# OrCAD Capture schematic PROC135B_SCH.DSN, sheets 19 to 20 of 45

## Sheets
19 19. eMMC FLASH: size C; title: SOC MMC0..2 INTERFACE, eMMC FLASH AND eMMC FLASH RESET
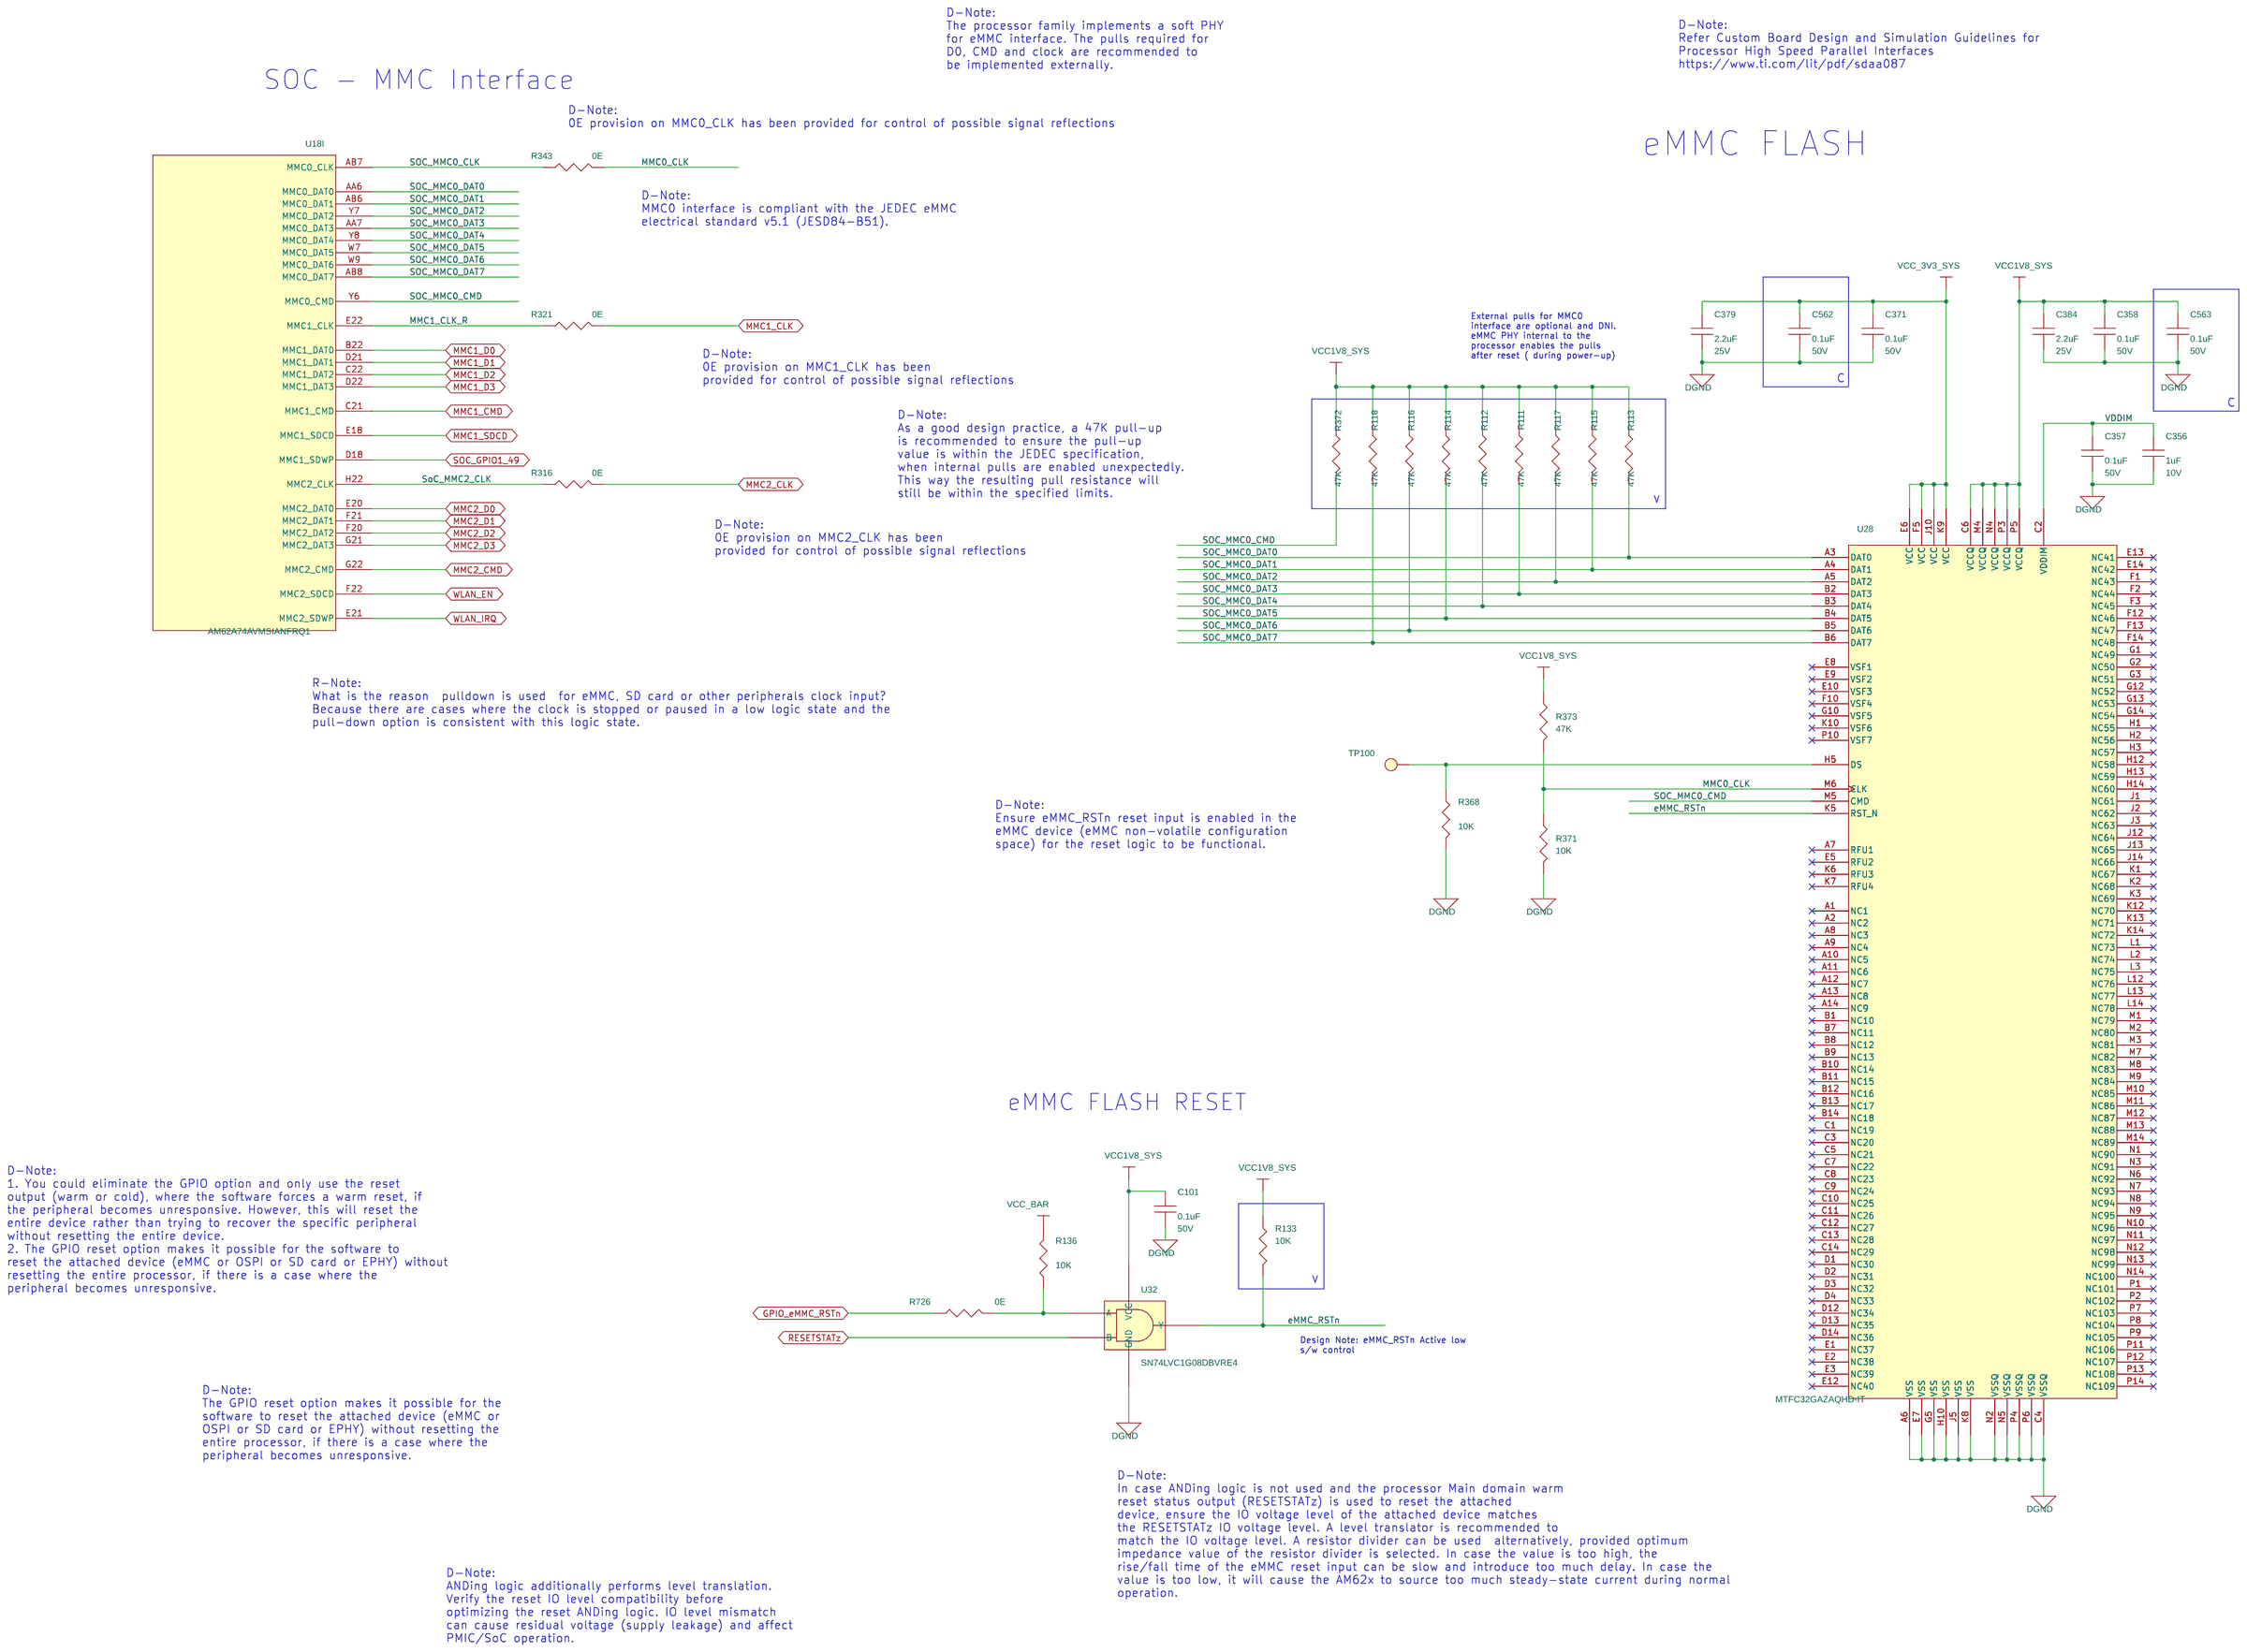
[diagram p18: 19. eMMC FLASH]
20 20. SD CARD INTERFACE: size C; title: SD CARD - LOAD SWITCH, LOAD SWITCH RESET LOGIC AND DATA INTERFACE
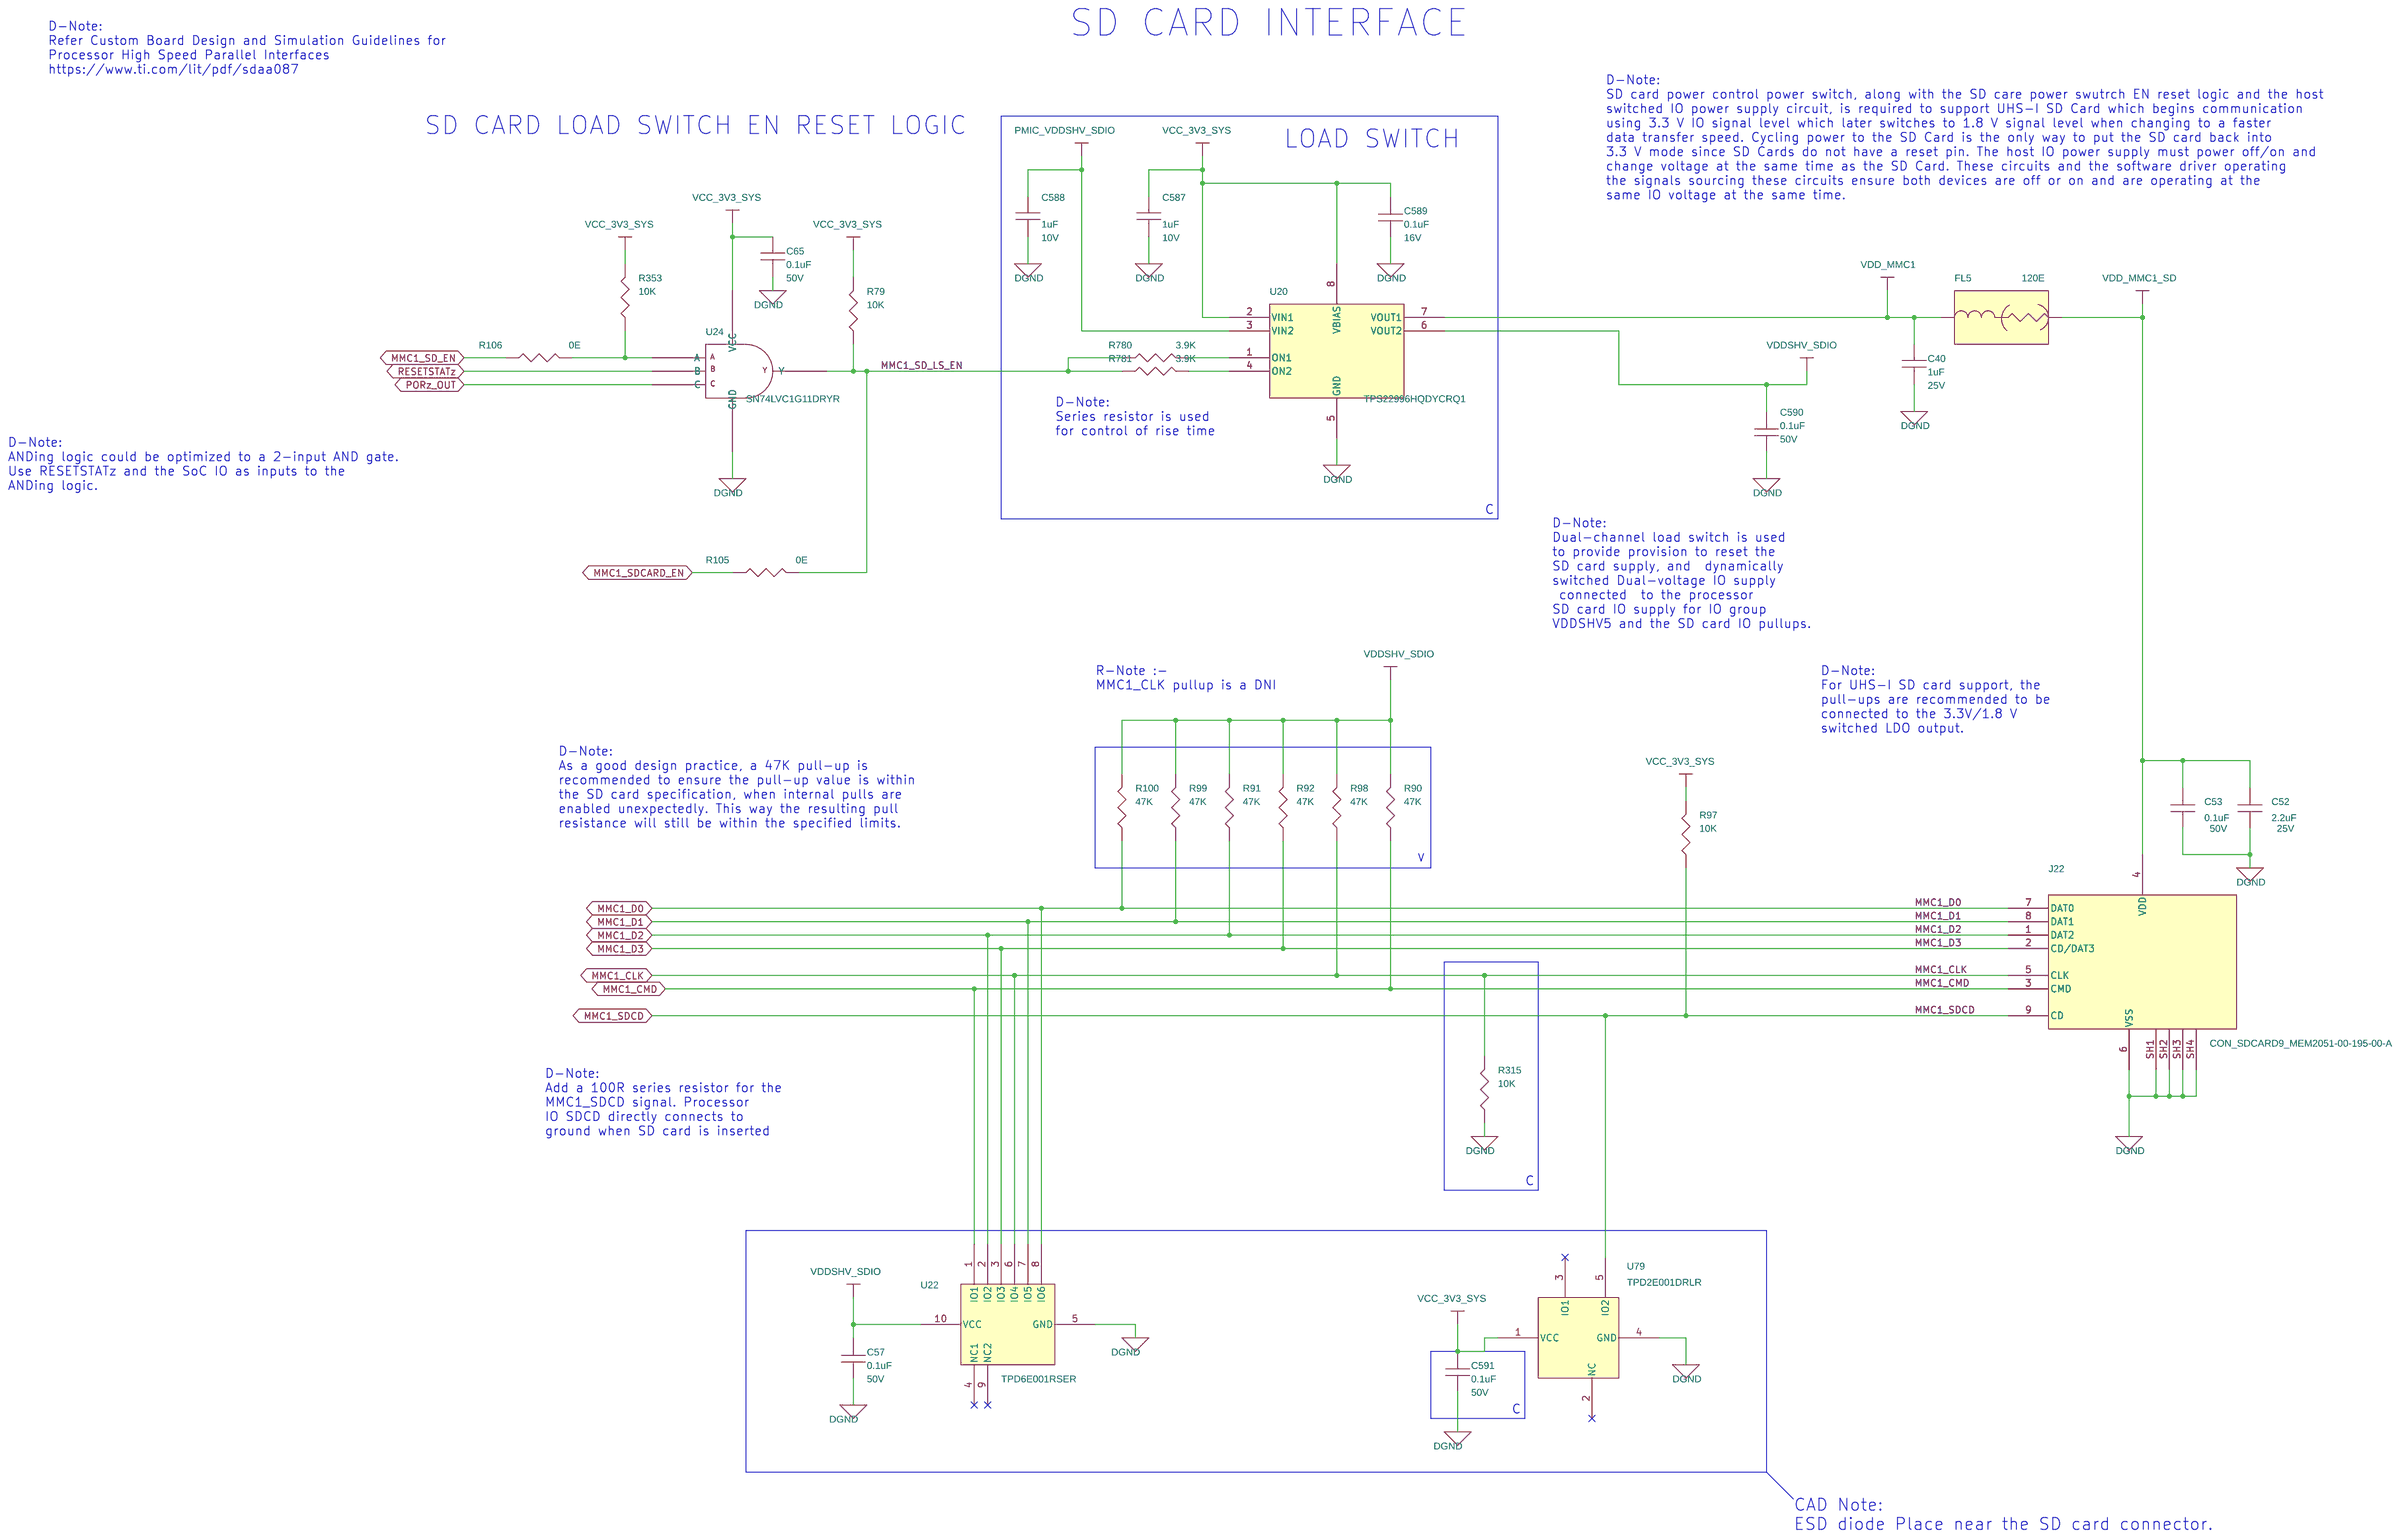
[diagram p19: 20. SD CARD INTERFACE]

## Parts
sheet 19. eMMC FLASH
C101  0.1uF  [CAP0402_0-75]
C356  1uF  [CAP0201_0-5]
C357  0.1uF  [CAP0402_0-75]
C358  0.1uF  [CAP0402_0-75]
C371  0.1uF  [CAP0402_0-75]
C379  2.2uF  [CAP0402_0-75]
C384  2.2uF  [CAP0402_0-75]
C562  0.1uF  [CAP0402_0-75]
C563  0.1uF  [CAP0402_0-75]
R111  47K  [RES0201_0-5]
R112  47K  [RES0201_0-5]
R113  47K  [RES0201_0-5]
R114  47K  [RES0201_0-5]
R115  47K  [RES0201_0-5]
R116  47K  [RES0201_0-5]
R117  47K  [RES0201_0-5]
R118  47K  [RES0201_0-5]
R133  10K  [RES0402_0-5]
R136  10K  [RES0201_0-5]
R316  0E  [RES0201_0-5]
R321  0E  [RES0201_0-5]
R343  0E  [RES0201_0-5]
R368  10K  [RES0201_0-5]
R371  10K  [RES0201_0-5]
R372  47K  [RES0201_0-5]
R373  47K  [RES0201_0-5]
R726  0E  [RES0402_0-5]
TP100  TP20_SMD  [TP20_SMD]
U28  MTFC32GAZAQHD-IT  [VFBGA153_19-68_460X520_0-9_CUSTOM]
U32  SN74LVC1G08DBVRE4  [SOT23-5]
sheet 20. SD CARD INTERFACE
C40  1uF  [CAP0402_0-75]
C52  2.2uF  [CAP0402_0-75]
C53  0.1uF  [CAP0402_0-75]
C57  0.1uF  [CAP0402_0-75]
C65  0.1uF  [CAP0402_0-75]
C587  1uF  [CAP0201_0-5]
C588  1uF  [CAP0201_0-5]
C589  0.1uF  [CAP0201_0-5]
C590  0.1uF  [CAP0402_0-75]
C591  0.1uF  [CAP0402_0-75]
FL5  120E  [EMIFIL_BLM15A_0402_0-6]
J22  CON_SDCARD9_MEM2051-00-195-00-A  [CON_SD9_MEM2051-00-195-00_S_R_S_2-1]
R79  10K  [RES0201_0-5]
R90  47K  [RES0201_0-5]
R91  47K  [RES0201_0-5]
R92  47K  [RES0201_0-5]
R97  10K  [RES0201_0-5]
R98  47K  [RES0201_0-5]
R99  47K  [RES0201_0-5]
R100  47K  [RES0201_0-5]
R105  0E  [RES0201_0-5]
R106  0E  [RES0201_0-5]
R315  10K  [RES0201_0-5]
R353  10K  [RES0201_0-5]
R780  3.9K  [RES0402_0-5]
R781  3.9K  [RES0402_0-5]
U20  TPS22996HQDYCRQ1  [SOT5X3-8_0-6]
U22  TPD6E001RSER  [UQFN10_19-68_80X60_0-6]
U24  SN74LVC1G11DRYR  [SON6_SN74LVC2G17_40X60_0-6]
U79  TPD2E001DRLR  [SOT553-5_0-6]
sheet 34. MCU HEADER
U18  AM62A74AVMSIANFRQ1  [FBGA484_31-49_710X710_2-7]  (sections A,B,C,D,E,F,G,H,I,J,K,L,M,N,O,P,Q)

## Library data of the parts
C53 C57 C65 C101 C357 C358 C371 C562 C563 C590 C591 = CAP: CAP CERAMIC 0.1uF 50V 10% X7R AUTO 0402; Alt_Mfr_name: YAGEO AMERICA; Alt_Mfr_part_number: CC0402KRX5R8BB104; Chkd/date: MANIRAJA/250221; Crtd /date: ALVY/240221; Custom_Duty: 15%; Customs_HS_Code: 85322990; Distributor_name: MOUSER; Distributor_part_number: 81-GRT155R71H104KE1D; Footprint Path: Y:\MIS_DATABASE\Library\ALTIUM_TOOL\PCB_FOOTPRINTS\Altium_Footprint_Lib.PcbLib; Height: 0.55MM; Library Path: Y:\MIS_DATABASE\Library\ALTIUM_TOOL\SCHEMATICS_PARTS\MS_DISCRETE_Library.schlib; Mfr_name: MURATA; Mfr_part_number: GRT155R71H104KE01D; Mistral Part No: 120019030005-R; Package: 0402; Part_type: CAPACITORS\CERAMIC; Project: TI_DRA821 SK EVM BRD; RoHS: RoHS; Temperature: -55°C+125°C; Tolerance: 10%; Voltage: 50V; Wattage: NA; Weight: NA; Datasheet: Y:\MIS_DATABASE\DATASHEETS\CAPACITORS\GRT155R71H104KE01.PDF
C356 C587 C588 = CAP: CAP CERAMIC 1uF 10V 20% X6S 0201; Chkd/date: PRADEEP/130623; Crtd /date: PRADEEP/130623; Custom_Duty: 15%; Customs_HS_Code: 85322990; Distributor_name: DIGIKEY; Distributor_part_number: 490-GRT033C81A105ME13DTR-ND; Footprint Path: Y:\MIS_DATABASE\Library\ALTIUM_TOOL\PCB_FOOTPRINTS\Altium_Footprint_Lib.PcbLib; Height: 0.39MM; Library Path: Y:\MIS_DATABASE\Library\ALTIUM_TOOL\SCHEMATICS_PARTS\MS_DISCRETE_Library.schlib; Mfr_name: MURATA; Mfr_part_number: GRT033C81A105ME13D; Mistral Part No: 120022060020-R; Package: 0201; Part_type: CAPACITORS\CERAMIC; Project: AM62P_SK; RoHS: RoHS; Temperature: -55°C+105°C; Tolerance: 20%; Voltage: 10V; Wattage: NA; Weight: NA; Datasheet: Y:\MIS_DATABASE\DATASHEETS\CAPACITORS\GRT033C81A105ME13D.PDF
C52 C379 C384 = CAP: CAP CERAMIC 2.2uF 25V 10% X5R AUTO 0402; Chkd/date: MANIRAJA/240920; Crtd /date: ALVY/240920; Custom_Duty: 15%; Customs_HS_Code: 85322990; Distributor_name: DIGIKEY; Distributor_part_number: 490-12267-1-ND; Footprint Path: Y:\MIS_DATABASE\Library\ALTIUM_TOOL\PCB_FOOTPRINTS\Altium_Footprint_Lib.PcbLib; Height: 0.70MM; Library Path: Y:\MIS_DATABASE\Library\ALTIUM_TOOL\SCHEMATICS_PARTS\MS_DISCRETE_Library.schlib; Mfr_name: MURATA; Mfr_part_number: GRT155R61E225KE13D; Mistral Part No: 120020090019-R; Package: 0402; Part_type: CAPACITORS\CERAMIC; Project: ECU_RO; RoHS: RoHS; Temperature: -55°C+85°C; Tolerance: 10%; Voltage: 25V; Wattage: NA; Weight: 0.65mg; Datasheet: Y:\MIS_DATABASE\DATASHEETS\CAPACITORS\GRT155R61E225KE13.PDF
R90-R92 R98-R100 R111-R118 R372 R373 = RESISTOR: RES 47K 1/20W 5% 0201; Chkd/date: MAZHAR/121207; Crtd /date: USMAN/121207; Custom_Duty: 15%; Customs_HS_Code: 85332119; Distributor_name: DIGIKEY; Distributor_part_number: P47KAGCT-ND; Footprint Path: Y:\MIS_DATABASE\Library\ALTIUM_TOOL\PCB_FOOTPRINTS\Altium_Footprint_Lib.PcbLib; Height: 0.26MM; Library Path: Y:\MIS_DATABASE\Library\ALTIUM_TOOL\SCHEMATICS_PARTS\MS_DISCRETE_Library.schlib; Mfr_name: PANASONIC-ECG; Mfr_part_number: ERJ-1GEJ473C; Mistral Part No: 110009030881-R; Package: 0201; Part_type: RESISTORS\FIXED; Project: SD_WATERLOO; RoHS: RoHS; Temperature: -55°C+125°C; Tolerance: 5%; Voltage: NA; Wattage: 1/20W; Weight: 0.15mg; Datasheet: Y:\MIS_DATABASE\DATASHEETS\RESISTORS\PAN-ERJXGE-FEB06.PDF
R133 = RESISTOR: RES 10K 1/16W 5% 0402; Chkd/date: MANIRAJA/120219; Crtd /date: MANIRAJA/120219; Custom_Duty: 15%; Customs_HS_Code: 85332119; Distributor_name: DIGIKEY; Distributor_part_number: 541-10KJCT-ND; Footprint Path: Y:\MIS_DATABASE\Library\ALTIUM_TOOL\PCB_FOOTPRINTS\Altium_Footprint_Lib.PcbLib; Height: 0.40MM; Library Path: Y:\MIS_DATABASE\Library\ALTIUM_TOOL\SCHEMATICS_PARTS\MS_DISCRETE_Library.schlib; Mfr_name: VISHAY; Mfr_part_number: CRCW040210K0JNED; Mistral Part No: 110011060021-R; Package: 0402; Part_type: RESISTORS\FIXED; Project: NEXTNAV_ORBIT_MODULE; RoHS: RoHS; Temperature: -55°C+155°C; Tolerance: 5%; Voltage: NA; Wattage: 1/16W; Weight: 0.65mg; Datasheet: Y:\MIS_DATABASE\DATASHEETS\RESISTORS\CRCW0603.PDF
R79 R97 R136 R315 R353 R368 R371 = RESISTOR: RES 10K 1/20W 5% 0201; Chkd/date: MANIRAJA/050517; Crtd /date: MANIRAJA/050517; Custom_Duty: 15%; Customs_HS_Code: 85332119; Distributor_name: DIGIKEY; Distributor_part_number: 311-10KNCT-ND; Footprint Path: Y:\MIS_DATABASE\Library\ALTIUM_TOOL\PCB_FOOTPRINTS\Altium_Footprint_Lib.PcbLib; Height: 0.26MM; Library Path: Y:\MIS_DATABASE\Library\ALTIUM_TOOL\SCHEMATICS_PARTS\MS_DISCRETE_Library.schlib; Mfr_name: YAGEO AMERICA; Mfr_part_number: RC0201JR-0710KL; Mistral Part No: 110010070051-R; Package: 0201; Part_type: RESISTORS\FIXED; Project: GOLDEN-I LITE; RoHS: RoHS; Temperature: -55°C+125°C; Tolerance: 5%; Voltage: NA; Wattage: 1/20W; Weight: 0.17mg; Datasheet: Y:\MIS_DATABASE\DATASHEETS\RESISTORS\RCXXXXL-SER_MAR18.PDF
R316 R321 = RESISTOR: RES 0E 1/20W 5% 0201; Chkd/date: NAVEED/301214; Crtd /date: MUDDU/120710; Custom_Duty: 15%; Customs_HS_Code: 85332119; Distributor_name: DIGIKEY; Distributor_part_number: 311-0.0NCT-ND; Footprint Path: Y:\MIS_DATABASE\Library\ALTIUM_TOOL\PCB_FOOTPRINTS\Altium_Footprint_Lib.PcbLib; Height: 0.26MM; Library Path: Y:\MIS_DATABASE\Library\ALTIUM_TOOL\SCHEMATICS_PARTS\MS_DISCRETE_Library.schlib; Mfr_name: YAGEO AMERICA; Mfr_part_number: RC0201JR-070RL; Mistral Part No: 110010070067-R; Package: 0201; Part_type: RESISTORS\FIXED; Project: PB_BUGBASE; RoHS: RoHS; SIGNAL_MODEL: RESISTOR_RES0201_0-5_0E_0E; Temperature: -55°C+125°C; Tolerance: 5%; Voltage: NA; Wattage: 1/20W; Weight: 0.17mg; Datasheet: Y:\MIS_DATABASE\DATASHEETS\RESISTORS\RCXXXXL-SER_MAR18.PDF
R343 = RESISTOR: RES 0E 1/20W 5% 0201; Chkd/date: NAVEED/301214; Crtd /date: MUDDU/120710; Custom_Duty: 15%; Customs_HS_Code: 85332119; Distributor_name: DIGIKEY; Distributor_part_number: 311-0.0NCT-ND; Footprint Path: Y:\MIS_DATABASE\Library\ALTIUM_TOOL\PCB_FOOTPRINTS\Altium_Footprint_Lib.PcbLib; Height: 0.26MM; Library Path: Y:\MIS_DATABASE\Library\ALTIUM_TOOL\SCHEMATICS_PARTS\MS_DISCRETE_Library.schlib; Mfr_name: YAGEO AMERICA; Mfr_part_number: RC0201JR-070RL; Mistral Part No: 110010070067-R; Package: 0201; Part_type: RESISTORS\FIXED; Project: PB_BUGBASE; RoHS: RoHS; SIGNAL_MODEL: RESISTOR_RES0201_0-5_22E_1%_22E_1%; Temperature: -55°C+125°C; Tolerance: 5%; Voltage: NA; Wattage: 1/20W; Weight: 0.17mg; Datasheet: Y:\MIS_DATABASE\DATASHEETS\RESISTORS\RCXXXXL-SER_MAR18.PDF
R726 = RESISTOR: RES 0E 1/16W JUMPER 0402; Chkd/date: VASANTHA/201216; Crtd /date: MUDDU/190810; Custom_Duty: 15%; Customs_HS_Code: 85332119; Distributor_name: DIGIKEY; Distributor_part_number: 541-0.0JCT-ND; Footprint Path: Y:\MIS_DATABASE\Library\ALTIUM_TOOL\PCB_FOOTPRINTS\Altium_Footprint_Lib.PcbLib; Height: 0.40MM; Library Path: Y:\MIS_DATABASE\Library\ALTIUM_TOOL\SCHEMATICS_PARTS\MS_DISCRETE_Library.schlib; Mfr_name: VISHAY; Mfr_part_number: CRCW04020000Z0ED; Mistral Part No: 110010080019-R; Package: 0402; Part_type: RESISTORS\FIXED; Project: PB_BUGBASE; RoHS: RoHS; Temperature: -55°C+155°C; Tolerance: NA; Voltage: NA; Wattage: 1/16W; Weight: 0.65mg; Datasheet: Y:\MIS_DATABASE\DATASHEETS\RESISTORS\CRCW0603.PDF
TP100 = TESTPOINT: TESTPOINT CIR 20 SMD; Chkd/date: SHREESHAIL/171006; Crtd /date: MAZHAR/171006; Custom_Duty: NA; Customs_HS_Code: NA; Distributor_name: NA; Distributor_part_number: NA; Footprint Path: Y:\MIS_DATABASE\Library\ALTIUM_TOOL\PCB_FOOTPRINTS\Altium_Footprint_Lib.PcbLib; Height: NA; Library Path: Y:\MIS_DATABASE\Library\ALTIUM_TOOL\SCHEMATICS_PARTS\MS_DISCRETE_Library.schlib; MECHANICAL 3D STEP FILE: NA; Mfr_name: LOCAL; Mistral Part No: NA; Package: SMD; Project: BT MODULE_CSRBC04; RoHS: NA; Temperature: NA; Tolerance: NA; Voltage: NA; Wattage: NA; Weight: NA; Datasheet: NA
U28 = MTFC16GAPALBH_TFBGA153: IC 32GB e-MMC MEMORY VFBGA153; Chkd/date: PRAVEEN/010922; Crtd /date: PRAVEEN/010922; Custom_Duty: 15%; Customs_HS_Code: 85423100; Distributor_name: DIGIKEY; Distributor_part_number: 557-MTFC32GAZAQHD-IT-ND; Footprint Path: Y:\MIS_DATABASE\Library\ALTIUM_TOOL\PCB_FOOTPRINTS\Altium_Footprint_Lib.PcbLib; Height: 0.90MM; Library Path: Y:\MIS_DATABASE\Library\ALTIUM_TOOL\SCHEMATICS_PARTS\MS_MISCMEMORY_Library.schlib; MECHANICAL 3D STEP FILE: VFBGA153_19-68_460X520_0-9; Mfr_name: MICRON; Mfr_part_number: MTFC32GAZAQHD-IT_CUSTOM; Mistral Part No: NA; Package: VFBGA153; Part_type: ICS\DIGITAL\MEMORY; Project: J7AEN_SK_EVM; RoHS: RoHS; Temperature: -40°C+95°C; Tolerance: NA; Voltage: NA; Wattage: NA; Weight: NA; Datasheet: Y:\MIS_DATABASE\DATASHEETS\ICS\MEMORY\MTFC64GAZAQHD-IT.PDF
U32 = SN74LVC1G08DBVRE4_SOT23-5: IC SINGLE 2-INPUT POSITIVE AND GATE SOT23-5; Chkd/date: SUHAS/221010; Crtd /date: USMAN/151008; Custom_Duty: 15%; Customs_HS_Code: 85423100; Distributor_name: DIGIKEY; Distributor_part_number: SN74LVC1G08DBVRE4-ND; Height: 1.45MM; Mfr_name: TEXAS INSTRUMENTS; Mistral Part No: 141009060026-R; Part_type: ICS\DIGITAL\GATES; Project: KHAN_MAIN; RoHS: Sb/ Br FREE; Temperature: -40°C+85°C; Datasheet: Y:\MIS_DATABASE\DATASHEETS\ICS\DIGITAL\GATES\SN74LVC1G08.PDF
C40 = CAP: CAP CERAMIC 1uF 25V 10% X5R AUTO 0402; Chkd/date: MANIRAJA/290318; Crtd /date: ALVY/280318; Custom_Duty: 15%; Customs_HS_Code: 85322990; Distributor_name: DIGIKEY; Distributor_part_number: 490-12263-1-ND; Footprint Path: Y:\MIS_DATABASE\Library\ALTIUM_TOOL\PCB_FOOTPRINTS\Altium_Footprint_Lib.PcbLib; Height: 0.55MM; Library Path: Y:\MIS_DATABASE\Library\ALTIUM_TOOL\SCHEMATICS_PARTS\MS_DISCRETE_Library.schlib; Mfr_name: MURATA; Mfr_part_number: GRT155R61E105KE01D; Mistral Part No: 120019040035-R; Package: 0402; Part_type: CAPACITORS\CERAMIC; Project: NPOL_SAR_ADC; RoHS: RoHS; Temperature: -55°C+85°C; Tolerance: 10%; Voltage: 25V; Wattage: NA; Weight: 0.65mg; Datasheet: Y:\MIS_DATABASE\DATASHEETS\CAPACITORS\GRT155R61E105KE01D.PDF
C589 = CAP: CAP CERAMIC 0.1uF 16V 10% X5R 0201; Alt_Mfr_name: YAGEO AMERICA; Alt_Mfr_part_number: CC0402KRX5R8BB104; Chkd/date: PRADEEP/130623; Crtd /date: PRADEEP/130623; Custom_Duty: 15%; Customs_HS_Code: 85322990; Distributor_name: NA; Distributor_part_number: NA; Footprint Path: Y:\MIS_DATABASE\Library\ALTIUM_TOOL\PCB_FOOTPRINTS\Altium_Footprint_Lib.PcbLib; Height: 0.33MM; Library Path: Y:\MIS_DATABASE\Library\ALTIUM_TOOL\SCHEMATICS_PARTS\MS_DISCRETE_Library.schlib; Mfr_name: MURATA; Mfr_part_number: GRT033R61C104KE01; Mistral Part No: 120022060019-R; Package: 0201; Part_type: CAPACITORS\CERAMIC; Project: AM62P_SK; RoHS: RoHS; Temperature: -55°C+85°C; Tolerance: 10%; Voltage: 16V; Wattage: NA; Weight: 0.33mg; Datasheet: Y:\MIS_DATABASE\DATASHEETS\CAPACITORS\GRT033R61C104KE01XX.PDF
FL5 = EMIFILTER_IND: IND FERRITE BEAD CHIP 120E 2A 0402; Crtd /date: SHANKARI/100425; Custom_Duty: 24%; Customs_HS_Code: 85369090; Distributor_name: DIGIKEY; Distributor_part_number: 490-16505-1-ND; Footprint Path: Y:\MIS_DATABASE\Library\ALTIUM_TOOL\PCB_FOOTPRINTS\Altium_Footprint_Lib.PcbLib; Height: 0.55MM; Library Path: Y:\MIS_DATABASE\Library\ALTIUM_TOOL\SCHEMATICS_PARTS\MS_FILTER_Library.schlib; Mfr_name: MURATA; Mfr_part_number: BLM15PX121SZ1D; Mistral Part No: 130025040021-R; Package: 0402; Part_type: INDUCTOR; Project: XWRL6844_EVM_PROTO; RoHS: RoHS; Temperature: -55°C+125°C; Tolerance: 25%; Voltage: NA; Wattage: NA; Weight: NA; Datasheet: Y:\MIS_DATABASE\DATASHEETS\DISCRETES\INDUCTORS\BLM15PX121SZ1D.PDF
J22 = CON_SDCARD9_MEM2075-00-140: CON MICROSD CARD 9POS FEMALE RT SMD; Chkd/date: MANIRAJA/270921; Crtd /date: ALVY/240921; Custom_Duty: 24%; Customs_HS_Code: 85369090; Distributor_name: DIGIKEY; Distributor_part_number: 2073-MEM2051-00-195-00-ACT-ND; Footprint Path: Y:\MIS_DATABASE\Library\ALTIUM_TOOL\PCB_FOOTPRINTS\Altium_Footprint_Lib.PcbLib; Height: 2.05MM; Library Path: Y:\MIS_DATABASE\Library\ALTIUM_TOOL\SCHEMATICS_PARTS\MS_CONNECTOR_Library.schlib; Mfr_name: GCT; Mfr_part_number: MEM2051-00-195-00-A; Mistral Part No: 150021090028-R; Package: SMD; Part_type: CONNECTOR\MEMORY CARD; Project: TI_AM62x SKEVM_BRD; RoHS: RoHS; Temperature: -40°C+85°C; Tolerance: NA; Voltage: NA; Wattage: NA; Weight: 1000mg; Datasheet: Y:\MIS_DATABASE\DATASHEETS\CONNECTORS\MEM2051-00-195-00-A.PDF
R105 R106 = RESISTOR: RES 0E 1/20W 5% 0201; Chkd/date: NAVEED/301214; Crtd /date: MUDDU/120710; Custom_Duty: 15%; Customs_HS_Code: 85332119; Distributor_name: DIGIKEY; Distributor_part_number: 311-0.0NCT-ND; Footprint Path: Y:\MIS_DATABASE\Library\ALTIUM_TOOL\PCB_FOOTPRINTS\Altium_Footprint_Lib.PcbLib; Height: 0.26MM; Library Path: Y:\MIS_DATABASE\Library\ALTIUM_TOOL\SCHEMATICS_PARTS\MS_DISCRETE_Library.schlib; Mfr_name: YAGEO AMERICA; Mfr_part_number: RC0201JR-070RL; Mistral Part No: 110010070067-R; Package: 0201; Part_type: RESISTORS\FIXED; Project: PB_BUGBASE; RoHS: RoHS; Temperature: -55°C+125°C; Tolerance: 5%; Voltage: NA; Wattage: 1/20W; Weight: 0.17mg; Datasheet: Y:\MIS_DATABASE\DATASHEETS\RESISTORS\RCXXXXL-SER_MAR18.PDF
R780 R781 = RESISTOR: RES 3.9K 1/16W 5% 0402; Chkd/date: PRADEEP/180725; Crtd /date: SHANKARI/170725; Custom_Duty: 15%; Customs_HS_Code: 85332119; Distributor_name: DIGIKEY; Distributor_part_number: 311-3.9KJRCT-ND; Footprint Path: Y:\MIS_DATABASE\Library\ALTIUM_TOOL\PCB_FOOTPRINTS\Altium_Footprint_Lib.PcbLib; Height: 0.40MM; Library Path: Y:\MIS_DATABASE\Library\ALTIUM_TOOL\SCHEMATICS_PARTS\MS_DISCRETE_Library.schlib; Mfr_name: YAGEO AMERICA; Mfr_part_number: RC0402JR-073K9L; Mistral Part No: 110025070048-R; Package: 0402; Part_type: RESISTORS\FIXED; Project: AM62X_SK_FULTON; RoHS: RoHS; Temperature: -55°C+155°C; Tolerance: 0.05; Voltage: NA; Wattage: 1/16W; Weight: NA; Datasheet: Y:\MIS_DATABASE\DATASHEETS\RESISTORS\RC0402JR-073K9L.PDF
U20 = TPS22996_SOT583-8: IC 5.5V 4A 13MO ON-RESISTANCE DUAL-CHANNEL AUTOMOTIVE LOAD SWITCH SOT583-8; Chkd/date: PRADEEP/170725; Crtd /date: SHANKARI/170725; Custom_Duty: 0.15; Customs_HS_Code: 85423100; Distributor_name: DIGIKEY; Distributor_part_number: 296-TPS22996HQDYCRQ1CT-ND; Footprint Path: Y:\MIS_DATABASE\Library\ALTIUM_TOOL\PCB_FOOTPRINTS\Altium_Footprint_Lib.PcbLib; Height: 0.60MM; Library Path: Y:\MIS_DATABASE\Library\ALTIUM_TOOL\SCHEMATICS_PARTS\MS_MISCPOWER_Library.schlib; Mfr_name: TEXAS INSTRUMENTS; Mistral Part No: 142025070014-R; Package: SOT583-8; Part_type: ICS\POWER\MANAGEMENT; Project: AM62X_SK_FULTON; RoHS: RoHS; Temperature: -40°C+125°C; Tolerance: NA; Voltage: NA; Wattage: NA; Weight: NA; Datasheet: Y:\MIS_DATABASE\DATASHEETS\ICS\POWER\TPS22996HQDYCRQ1.PDF
U22 = TPD6E001RSE_UQFN10: IC 6CH ESD-PROTECTION ARRAY UQFN10; Chkd/date: USMAN/070612; Crtd /date: BAVISH/160811; Custom_Duty: 15%; Customs_HS_Code: 85423100; Distributor_name: DIGIKEY; Distributor_part_number: 296-21888-1-ND; Footprint Path: Y:\MIS_DATABASE\Library\ALTIUM_TOOL\PCB_FOOTPRINTS\Altium_Footprint_Lib.PcbLib; Height: 0.60MM; IBISSP_MODLES: Y:\MIS_DATABASE\IBIS\ICs\INTERFACE\TPD6E001RSE.IBS; Library Path: Y:\MIS_DATABASE\Library\ALTIUM_TOOL\SCHEMATICS_PARTS\MS_MISCINTERFACE_Library.schlib; Mfr_name: TEXAS INSTRUMENTS; Mistral Part No: 141011080020-R; Package: UQFN10; Part_type: ICS\INTERFACE; Project: DM385EVM_BASE-BOARD; RoHS: RoHS; Temperature: -40°C+85°C; Tolerance: NA; Voltage: NA; Wattage: NA; Weight: 7mg; Datasheet: Y:\MIS_DATABASE\DATASHEETS\ICS\INTERFACE\TPD6E001.PDF
U24 = SN74LVC1G11DCKR_SC70-6: IC SINGLE 3-INPUT POSITIVE-AND GATE SON6; Chkd/date: MANIRAJA/270121; Crtd /date: ALVY/270121; Custom_Duty: 15%; Customs_HS_Code: 85423100; Distributor_name: DIGIKEY; Distributor_part_number: 296-30120-1-ND; Footprint Path: Y:\MIS_DATABASE\Library\ALTIUM_TOOL\PCB_FOOTPRINTS\Altium_Footprint_Lib.PcbLib; Height: 0.60MM; Library Path: Y:\MIS_DATABASE\Library\ALTIUM_TOOL\SCHEMATICS_PARTS\MS_GATE_Library.schlib; Mfr_name: TEXAS INSTRUMENTS; Mistral Part No: 141021010013-R; Package: SON6; Part_type: ICS\DIGITAL\GATES; Project: AM64X_SKEVM; RoHS: RoHS; Temperature: -40°C+125°C; Tolerance: NA; Voltage: NA; Wattage: NA; Weight: 33mg; Datasheet: Y:\MIS_DATABASE\DATASHEETS\ICS\DIGITAL\GATES\SN74LVC1G_NOV16.PDF
U79 = TPD2E001DRLR_SOT-5: IC ESD-PROTECTION DIODE ARRAYS SOT-5; Chkd/date: NAVEED/150714; Crtd /date: MUDDU/250510; Custom_Duty: 15%; Customs_HS_Code: 85423100; Distributor_name: DIGIKEY; Distributor_part_number: 296-21883-1-ND; Footprint Path: Y:\MIS_DATABASE\Library\ALTIUM_TOOL\PCB_FOOTPRINTS\Altium_Footprint_Lib.PcbLib; Height: 0.60MM; Library Path: Y:\MIS_DATABASE\Library\ALTIUM_TOOL\SCHEMATICS_PARTS\MS_FILTER_Library.schlib; Mfr_name: TEXAS INSTRUMENTS; Mistral Part No: 140110060007-R; Package: SOT-5; Part_type: ICS\ANALOG\ACTIVE FILTER; Project: CENTAURUS; RoHS: RoHS; Temperature: -40°C+85°C; Tolerance: NA; Voltage: NA; Wattage: NA; Weight: 2.8mg; Datasheet: Y:\MIS_DATABASE\DATASHEETS\ICS\MISC\TPD2E001DRLR.PDF
U18 = AM62A-EVM_SOC_FCBGA484: IC AM62A SK EVM SoC MICROPROCESSOR FCBGA484; Chkd/date: PRADEEP/120225; Crtd /date: SHANKARI/120225; Custom_Duty: 15%; Customs_HS_Code: 85369090; Distributor_name: NA; Distributor_part_number: NA; Footprint Path: Y:\MIS_DATABASE\Library\ALTIUM_TOOL\PCB_FOOTPRINTS\Altium_Footprint_Lib.PcbLib; Height: 2.65MM; Library Path: Y:\MIS_DATABASE\Library\ALTIUM_TOOL\SCHEMATICS_PARTS\MS_MICROPROCESSOR_Library.schlib; Library Ref: AM62A-EVM_SoC_FCBGA484; Mfr_name: TEXAS INSTRUMENTS; Mistral Part No: 141225020003-R; Package: FCBGA484; Part_type: ICS\DIGITAL\MICROPROCESSOR; Project: AM62A_SK_EVM; RoHS: NA; Temperature: NA; Tolerance: NA; Voltage: NA; Wattage: NA; Weight: NA; Datasheet: Y:\MIS_DATABASE\DATASHEETS\ICS\DIGITAL\MICROCONTROLLER\AM62A_SK_EVM.PDF

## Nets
DGND: C40.2 C52.1 C53.1 C57.1 C65.2 C101.2 C356.2 C357.2 C358.2 C371.2 C379.2 C384.2 C562.2 C563.2 C587.2 C588.2 C589.1 C590.1 C591.1 J22.6(VSS) J22.SH1 J22.SH2 J22.SH3 J22.SH4 R315.2 R368.2 R371.2 U20.5(GND) U22.5(GND) U24.2(GND) U28.A6(VSS) U28.C4(VSSQ) U28.E7(VSS) U28.G5(VSS) U28.H10(VSS) U28.J5(VSS) U28.K8(VSS) U28.N2(VSSQ) U28.N5(VSSQ) U28.P4(VSSQ) U28.P6(VSSQ) U32.3(GND) U79.4(GND) ; also on sheet 10 11 12 13 14 15 16 17 18 21 22 23 24 25 26 27 28 29 30 31 32 33 34 35 36 37 38 39 40 41 42 43 44
VCC1V8_SYS: C101.1 C358.1 C384.1 C563.1 R111.1 R112.1 R113.1 R114.1 R115.1 R116.1 R117.1 R118.1 R133.1 R372.1 R373.1 U28.C6(VCCQ) U28.M4(VCCQ) U28.N4(VCCQ) U28.P3(VCCQ) U28.P5(VCCQ) U32.5(VCC) ; also on sheet 13 18 21 34 37 39 40 42
VCC_3V3_SYS: C65.1 C371.1 C379.1 C562.1 C587.1 C589.2 C591.2 R79.2 R97.2 R136.2 R353.2 U20.2(VIN1) U20.8(VBIAS) U24.5(VCC) U28.E6(VCC) U28.F5(VCC) U28.J10(VCC) U28.K9(VCC) U79.1(VCC) ; also on sheet 10 11 13 14 18 22 23 24 26 27 29 30 31 33 34 35 36 37 38 39 40 41 42 43
VDD_MMC1: C40.1 FL5.1 U20.7(VOUT1)
VDD_MMC1_SD: C52.2 C53.2 FL5.2 J22.4(VDD)
VDDIM: C356.1 C357.1 U28.C2(VDDIM)
VDDSHV_SDIO: C57.2 C590.2 R90.2 R91.2 R92.2 R98.2 R99.2 R100.2 U20.6(VOUT2) U22.10(VCC) ; also on sheet 15
eMMC_RSTn: R133.2 U28.K5(RST_N) U32.4(Y)
GPIO_eMMC_RSTn: R726.2 ; also on sheet 40
MMC0_CLK: R343.1 R371.1 R373.2 U28.M6(CLK)
MMC1_CLK: J22.5(CLK) R98.1 R315.1 R321.1 U22.6(IO4)
MMC1_CLK_R: R321.2 U18.E22(MMC1_CLK)
MMC1_CMD: J22.3(CMD) R90.1 U18.C21(MMC1_CMD) U22.1(IO1)
MMC1_D0: J22.7(DAT0) R100.1 U18.B22(MMC1_DAT0) U22.8(IO6)
MMC1_D1: J22.8(DAT1) R99.1 U18.D21(MMC1_DAT1) U22.7(IO5)
MMC1_D2: J22.1(DAT2) R91.1 U18.C22(MMC1_DAT2) U22.2(IO2)
MMC1_D3: J22.2(CD/DAT3) R92.1 U18.D22(MMC1_DAT3) U22.3(IO3)
MMC1_SD_EN: R106.1 ; also on sheet 40
MMC1_SD_LS_EN: R79.1 R105.2 R780.1 R781.1 U24.4(Y)
MMC1_SDCARD_EN: R105.1 ; also on sheet 13
MMC1_SDCD: J22.9(CD) R97.1 U18.E18(MMC1_SDCD) U79.5(IO2)
MMC2_CLK: R316.2 ; also on sheet 18
MMC2_CMD: U18.G22(MMC2_CMD) ; also on sheet 18
MMC2_D0: U18.E20(MMC2_DAT0) ; also on sheet 18
MMC2_D1: U18.F21(MMC2_DAT1) ; also on sheet 18
MMC2_D2: U18.F20(MMC2_DAT2) ; also on sheet 18
MMC2_D3: U18.G21(MMC2_DAT3) ; also on sheet 18
PMIC_VDDSHV_SDIO: C588.1 U20.3(VIN2) ; also on sheet 13
PORz_OUT: U24.6(C) ; also on sheet 23 24 27 42
RESETSTATz: U24.3(B) U32.2(B) ; also on sheet 21 23 24 27 38 39 40 41 42
SOC_GPIO1_49: U18.D18(MMC1_SDWP) ; also on sheet 36
SOC_MMC0_CLK: R343.2 U18.AB7(MMC0_CLK)
SOC_MMC0_CMD: R372.2 U18.Y6(MMC0_CMD) U28.M5(CMD)
SOC_MMC0_DAT0: R113.2 U18.AA6(MMC0_DAT0) U28.A3(DAT0)
SOC_MMC0_DAT1: R115.2 U18.AB6(MMC0_DAT1) U28.A4(DAT1)
SOC_MMC0_DAT2: R117.2 U18.Y7(MMC0_DAT2) U28.A5(DAT2)
SOC_MMC0_DAT3: R111.2 U18.AA7(MMC0_DAT3) U28.B2(DAT3)
SOC_MMC0_DAT4: R112.2 U18.Y8(MMC0_DAT4) U28.B3(DAT4)
SOC_MMC0_DAT5: R114.2 U18.W7(MMC0_DAT5) U28.B4(DAT5)
SOC_MMC0_DAT6: R116.2 U18.W9(MMC0_DAT6) U28.B5(DAT6)
SOC_MMC0_DAT7: R118.2 U18.AB8(MMC0_DAT7) U28.B6(DAT7)
SoC_MMC2_CLK: R316.1 U18.H22(MMC2_CLK)
WLAN_EN: U18.F22(MMC2_SDCD) ; also on sheet 18
WLAN_IRQ: U18.E21(MMC2_SDWP) ; also on sheet 18
N16848941: R136.1 R726.1 U32.1(A)
N16878497: R368.1 TP100.1(TP) U28.H5(DS)
N16880083: R106.2 R353.1 U24.1(A)
N24645896: R781.2 U20.4(ON2)
N24645912: R780.2 U20.1(ON1)

Not connected (* = marked no-connect by the designer): U22 4(NC1)* 9(NC2)*; U28 A1(NC1)* A2(NC2)* A7(RFU1)* A8(NC3)* A9(NC4)* A10(NC5)* A11(NC6)* A12(NC7)* A13(NC8)* A14(NC9)* B1(NC10)* B7(NC11)* B8(NC12)* B9(NC13)* B10(NC14)* B11(NC15)* B12(NC16)* B13(NC17)* B14(NC18)* C1(NC19)* C3(NC20)* C5(NC21)* C7(NC22)* C8(NC23)* C9(NC24)* C10(NC25)* C11(NC26)* C12(NC27)* C13(NC28)* C14(NC29)* D1(NC30)* D2(NC31)* D3(NC32)* D4(NC33)* D12(NC34)* D13(NC35)* D14(NC36)* E1(NC37)* E2(NC38)* E3(NC39)* E5(RFU2)* E8(VSF1)* E9(VSF2)* E10(VSF3)* E12(NC40)* E13(NC41)* E14(NC42)* F1(NC43)* F2(NC44)* F3(NC45)* F10(VSF4)* F12(NC46)* F13(NC47)* F14(NC48)* G1(NC49)* G2(NC50)* G3(NC51)* G10(VSF5)* G12(NC52)* G13(NC53)* G14(NC54)* H1(NC55)* H2(NC56)* H3(NC57)* H12(NC58)* H13(NC59)* H14(NC60)* J1(NC61)* J2(NC62)* J3(NC63)* J12(NC64)* J13(NC65)* J14(NC66)* K1(NC67)* K2(NC68)* K3(NC69)* K6(RFU3)* K7(RFU4)* K10(VSF6)* K12(NC70)* K13(NC71)* K14(NC72)* L1(NC73)* L2(NC74)* L3(NC75)* L12(NC76)* L13(NC77)* L14(NC78)* M1(NC79)* M2(NC80)* M3(NC81)* M7(NC82)* M8(NC83)* M9(NC84)* M10(NC85)* M11(NC86)* M12(NC87)* M13(NC88)* M14(NC89)* N1(NC90)* N3(NC91)* N6(NC92)* N7(NC93)* N8(NC94)* N9(NC95)* N10(NC96)* N11(NC97)* N12(NC98)* N13(NC99)* N14(NC100)* P1(NC101)* P2(NC102)* P7(NC103)* P8(NC104)* P9(NC105)* P10(VSF7)* P11(NC106)* P12(NC107)* P13(NC108)* P14(NC109)*; U79 2(NC)* 3(IO1)*

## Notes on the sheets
sheet 19
- D-Note:
  The processor family implements a soft PHY
  for eMMC interface. The pulls required for
  D0, CMD and clock are recommended to
  be implemented externally.
- D-Note:
  Refer Custom Board Design and Simulation Guidelines for
  Processor High Speed Parallel Interfaces
  https://www.ti.com/lit/pdf/sdaa087
- SOC - MMC Interface
- D-Note:
  0E provision on MMC0_CLK has been provided for control of possible signal reflections
- eMMC FLASH
- D-Note:
  MMC0 interface is compliant with the JEDEC eMMC
  electrical standard v5.1 (JESD84-B51).
- External pulls for MMC0
  interface are optional and DNI.
  eMMC PHY internal to the
  processor enables the pulls
  after reset ( during power-up)
- D-Note:
  0E provision on MMC1_CLK has been
  provided for control of possible signal reflections
- C
- C
- D-Note:
  As a good design practice, a 47K pull-up
  is recommended to ensure the pull-up
  value is within the JEDEC specification,
  when internal pulls are enabled unexpectedly.
  This way the resulting pull resistance will
  still be within the specified limits.
- V
- D-Note:
  0E provision on MMC2_CLK has been
  provided for control of possible signal reflections
- R-Note:
  What is the reason  pulldown is used  for eMMC, SD card or other peripherals clock input?
  Because there are cases where the clock is stopped or paused in a low logic state and the
  pull-down option is consistent with this logic state.
- D-Note:
  Ensure eMMC_RSTn reset input is enabled in the
  eMMC device (eMMC non-volatile configuration
  space) for the reset logic to be functional.
- eMMC FLASH RESET
- D-Note:
  1. You could eliminate the GPIO option and only use the reset
  output (warm or cold), where the software forces a warm reset, if
  the peripheral becomes unresponsive. However, this will reset the
  entire device rather than trying to recover the specific peripheral
  without resetting the entire device.
  2. The GPIO reset option makes it possible for the software to
  reset the attached device (eMMC or OSPI or SD card or EPHY) without
  resetting the entire processor, if there is a case where the
  peripheral becomes unresponsive.
- V
- Design Note: eMMC_RSTn Active low
  s/w control
- D-Note:
  The GPIO reset option makes it possible for the
  software to reset the attached device (eMMC or
  OSPI or SD card or EPHY) without resetting the
  entire processor, if there is a case where the
  peripheral becomes unresponsive.
- D-Note:
  In case ANDing logic is not used and the processor Main domain warm
  reset status output (RESETSTATz) is used to reset the attached
  device, ensure the IO voltage level of the attached device matches
  the RESETSTATz IO voltage level. A level translator is recommended to
  match the IO voltage level. A resistor divider can be used  alternatively, provided optimum
  impedance value of the resistor divider is selected. In case the value is too high, the
  rise/fall time of the eMMC reset input can be slow and introduce too much delay. In case the
  value is too low, it will cause the AM62x to source too much steady-state current during normal
  operation.
- D-Note:
  ANDing logic additionally performs level translation.
  Verify the reset IO level compatibility before
  optimizing the reset ANDing logic. IO level mismatch
  can cause residual voltage (supply leakage) and affect
  PMIC/SoC operation.
sheet 20
- SD CARD INTERFACE
- D-Note:
  Refer Custom Board Design and Simulation Guidelines for
  Processor High Speed Parallel Interfaces
  https://www.ti.com/lit/pdf/sdaa087
- D-Note:
  SD card power control power switch, along with the SD care power swutrch EN reset logic and the host
  switched IO power supply circuit, is required to support UHS-I SD Card which begins communication
  using 3.3 V IO signal level which later switches to 1.8 V signal level when changing to a faster
  data transfer speed. Cycling power to the SD Card is the only way to put the SD card back into
  3.3 V mode since SD Cards do not have a reset pin. The host IO power supply must power off/on and
  change voltage at the same time as the SD Card. These circuits and the software driver operating
  the signals sourcing these circuits ensure both devices are off or on and are operating at the
  same IO voltage at the same time.
- SD CARD LOAD SWITCH EN RESET LOGIC
- LOAD SWITCH
- D-Note:
  Series resistor is used
  for control of rise time
- D-Note:
  ANDing logic could be optimized to a 2-input AND gate.
  Use RESETSTATz and the SoC IO as inputs to the
  ANDing logic.
- C
- D-Note:
  Dual-channel load switch is used
  to provide provision to reset the
  SD card supply, and  dynamically
  switched Dual-voltage IO supply
   connected  to the processor
  SD card IO supply for IO group
  VDDSHV5 and the SD card IO pullups.
- R-Note :-
  MMC1_CLK pullup is a DNI
- D-Note:
  For UHS-I SD card support, the
  pull-ups are recommended to be
  connected to the 3.3V/1.8 V
  switched LDO output.
- D-Note:
  As a good design practice, a 47K pull-up is
  recommended to ensure the pull-up value is within
  the SD card specification, when internal pulls are
  enabled unexpectedly. This way the resulting pull
  resistance will still be within the specified limits.
- V
- D-Note:
  Add a 100R series resistor for the
  MMC1_SDCD signal. Processor
  IO SDCD directly connects to
  ground when SD card is inserted
- C
- C
- CAD Note:
  ESD diode Place near the SD card connector.
